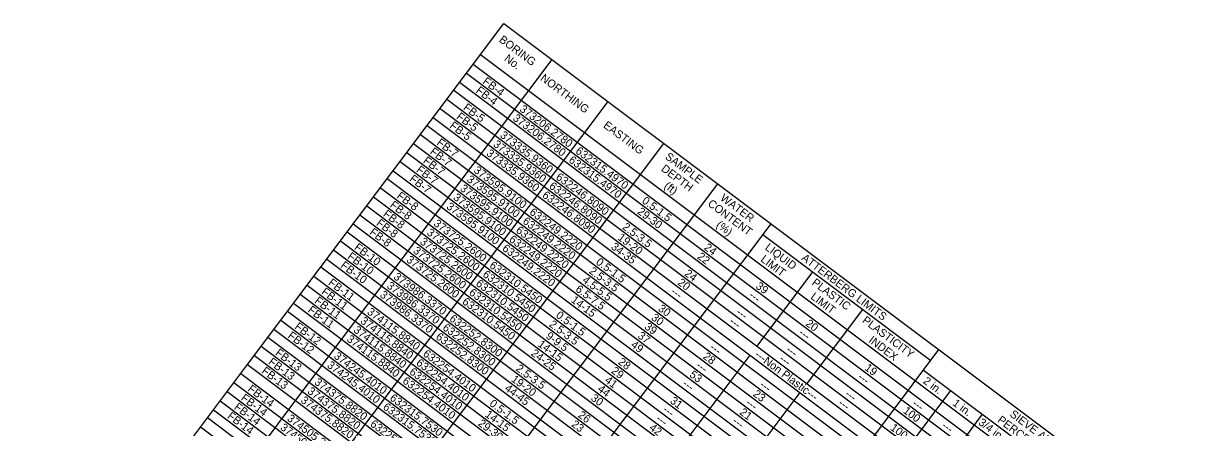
# Model space of a CAD drawing. Extents: x 627484.2 to 627517.5, y 367968.7 to 367996.9.
# Drawn here: x 627484.17 to 627492.24, y 367994.12 to 367996.9 of the extents above; entities that cross this region are included whole.
import ezdxf

# ---------------------------------------------------------------- set-up
doc = ezdxf.new("R2010")
doc.units = 0
doc.layers.add('Default', color=7, linetype='Continuous')
doc.layers.add('R_Survey Control', color=7, linetype='Continuous')

msp = doc.modelspace()

# ---------------------------------------------------------------- linework, layer by layer
at = {"layer": 'Default'}
for p, q in [((627485.7146, 367994.5544), (627487.4769, 367996.9012)), ((627487.4769, 367996.9012), (627492.7198, 367992.9642)), ((627485.9992, 367994.2432), (627487.8082, 367996.6524)), ((627487.3159, 367996.6868), (627492.5588, 367992.7498)), ((627487.2661, 367996.6205), (627491.6592, 367993.3217)), ((627487.1724, 367996.4958), (627492.4153, 367992.5588)), ((627487.2193, 367996.5581), (627491.4252, 367993.3998)), ((627487.1314, 367996.4412), (627492.3744, 367992.5042)), ((627486.383, 367993.955), (627488.192, 367996.3641)), ((627487.0846, 367996.3788), (627492.3275, 367992.4419)), ((627486.9909, 367996.2541), (627492.2338, 367992.3171)), ((627487.0378, 367996.3164), (627492.2807, 367992.3795)), ((627486.95, 367996.1995), (627492.1929, 367992.2625)), ((627486.9031, 367996.1371), (627492.146, 367992.2002)), ((627486.7668, 367993.6668), (627488.5759, 367996.0759)), ((627486.8094, 367996.0124), (627492.0524, 367992.0754)), ((627486.8563, 367996.0747), (627492.0992, 367992.1378)), ((627486.7626, 367995.95), (627492.0055, 367992.013)), ((627486.7158, 367995.8876), (627491.9587, 367991.9507)), ((627486.628, 367995.7707), (627491.8709, 367991.8337)), ((627486.6748, 367995.833), (627491.9177, 367991.8961)), ((627487.1372, 367993.3887), (627488.9462, 367995.7978)), ((627486.5811, 367995.7083), (627491.824, 367991.7713)), ((627486.5343, 367995.6459), (627491.7772, 367991.709)), ((627486.4406, 367995.5212), (627491.6835, 367991.5842)), ((627486.4874, 367995.5836), (627491.7304, 367991.6466)), ((627487.5036, 367993.1135), (627489.3127, 367995.5227)), ((627486.3996, 367995.4666), (627491.6425, 367991.5297)), ((627489.257, 367995.4486), (627490.4109, 367994.5821)), ((627486.3528, 367995.4042), (627491.5957, 367991.4673)), ((627486.2591, 367995.2795), (627491.502, 367991.3425)), ((627486.306, 367995.3419), (627491.5489, 367991.4049)), ((627486.2181, 367995.2249), (627491.461, 367991.288)), ((627486.1713, 367995.1625), (627491.4142, 367991.2256)), ((627489.2166, 367994.6803), (627489.6001, 367995.191)), ((627486.0776, 367995.0378), (627491.3205, 367991.1008)), ((627486.1245, 367995.1002), (627491.3674, 367991.1632)), ((627486.0308, 367994.9754), (627491.2737, 367991.0385)), ((627485.9898, 367994.9208), (627491.2327, 367990.9839)), ((627489.5597, 367994.4227), (627489.9431, 367994.9334)), ((627485.8961, 367994.7961), (627491.139, 367990.8591)), ((627485.943, 367994.8585), (627491.1859, 367990.9215)), ((627485.8552, 367994.7415), (627491.0981, 367990.8046)), ((627485.8083, 367994.6791), (627491.0512, 367990.7422)), ((627488.6575, 367992.247), (627490.4666, 367994.6562)), ((627484.1749, 367992.5039), (627485.7146, 367994.5544)), ((627485.7146, 367994.5544), (627490.9576, 367990.6175)), ((627485.7615, 367994.6168), (627491.0044, 367990.6798)), ((627488.1687, 367993.2847), (627489.1698, 367994.6179)), ((627485.6678, 367994.492), (627490.9107, 367990.5551)), ((627490.3612, 367994.5159), (627491.9517, 367993.3215)), ((627485.621, 367994.4297), (627490.8639, 367990.4927)), ((627485.5741, 367994.3673), (627490.817, 367990.4303)), ((627488.5117, 367993.0271), (627489.5128, 367994.3603)), ((627488.8446, 367992.1065), (627490.5483, 367994.3753)), ((627484.5063, 367992.2551), (627485.9992, 367994.2432)), ((627485.4805, 367994.2425), (627490.7234, 367990.3056)), ((627485.5273, 367994.3049), (627490.7702, 367990.368)), ((627485.4395, 367994.188), (627490.6824, 367990.251)), ((627489.0629, 367991.9426), (627490.7666, 367994.2114)), ((627485.3926, 367994.1256), (627490.6356, 367990.1886))]:
    msp.add_line(p, q, dxfattribs=at)
at = {"layer": 'R_Survey Control'}
msp.add_line((627488.2445, 367996.3247), (627488.2445, 367996.3247), dxfattribs=at)

# ---------------------------------------------------------------- texts
at = {"layer": 'Default'}
for s, p in [('BORING', (627487.4387, 367996.7794)), ('No.', (627487.4743, 367996.6495)), ('FB-4', (627487.3262, 367996.4922)), ('NORTHING', (627487.7227, 367996.5145)), ('FB-4', (627487.2794, 367996.4298)), ('FB-5', (627487.1926, 367996.3121)), ('373206.2780', (627487.58, 367996.3016)), ('FB-5', (627487.1457, 367996.2498)), ('373206.2780', (627487.5332, 367996.2392)), ('FB-5', (627487.0989, 367996.1874)), ('EASTING', (627488.1548, 367996.1901)), ('FB-7', (627487.0104, 367996.0709)), ('373335.9360', (627487.3985, 367996.0599)), ('373335.9360', (627487.4454, 367996.1223)), ('FB-7', (627486.9635, 367996.0086)), ('373335.9360', (627487.3517, 367995.9976)), ('632315.4970', (627487.9638, 367996.0134)), ('SAMPLE', (627488.5795, 367995.9743)), ('FB-7', (627486.8699, 367995.8838)), ('FB-7', (627486.9167, 367995.9462)), ('632315.4970', (627487.917, 367995.951)), ('DEPTH', (627488.5526, 367995.8913)), ('FB-7', (627486.823, 367995.8215)), ('373595.9100', (627487.217, 367995.8182)), ('373595.9100', (627487.2639, 367995.8806)), ('632246.8090', (627487.8292, 367995.8341)), ('373595.9100', (627487.1702, 367995.7559)), ('632246.8090', (627487.7824, 367995.7717)), ('(ft)', (627488.5724, 367995.7733)), ('FB-8', (627486.6888, 367995.6418)), ('FB-8', (627486.7356, 367995.7042)), ('373595.9100', (627487.1234, 367995.6935)), ('632246.8090', (627487.7355, 367995.7093)), ('0.5-1.5', (627488.4205, 367995.6705)), ('CONTENT', (627488.8728, 367995.6509)), ('WATER', (627488.9588, 367995.6895)), ('FB-8', (627486.6419, 367995.5795)), ('373595.9100', (627487.0765, 367995.6311)), ('632249.2220', (627487.6477, 367995.5924)), ('29-30', (627488.3889, 367995.5967)), ('FB-8', (627486.5951, 367995.5171)), ('373725.2600', (627486.9887, 367995.5142)), ('632249.2220', (627487.6009, 367995.53)), ('2.5-3.5', (627488.2858, 367995.4912)), ('(%)', (627488.93, 367995.5048)), ('FB-8', (627486.5483, 367995.4547)), ('373725.2600', (627486.9419, 367995.4518)), ('632249.2220', (627487.5072, 367995.4053)), ('632249.2220', (627487.554, 367995.4676)), ('19-20', (627488.2542, 367995.4174)), ('FB-10', (627486.4435, 367995.3505)), ('373725.2600', (627486.8482, 367995.327)), ('373725.2600', (627486.895, 367995.3894)), ('632249.2220', (627487.4604, 367995.3429)), ('34-35', (627488.2084, 367995.3543)), ('24', (627488.8474, 367995.3499)), ('LIQUID', (627489.2662, 367995.3492)), ('FB-10', (627486.3967, 367995.2881)), ('373725.2600', (627486.8014, 367995.2647)), ('0.5-1.5', (627488.1043, 367995.2495)), ('22', (627488.8008, 367995.2874)), ('LIMIT', (627489.2363, 367995.2684)), ('ATTERBERG LIMITS', (627489.5167, 367995.2771)), ('FB-10', (627486.3498, 367995.2257)), ('632310.5450', (627487.3257, 367995.1636)), ('632310.5450', (627487.3725, 367995.2259)), ('2.5-3.5', (627488.0575, 367995.1871)), ('24', (627488.7127, 367995.1706)), ('FB-11', (627486.2648, 367995.1067)), ('373986.3370', (627486.6667, 367995.0853)), ('373986.3370', (627486.7135, 367995.1477)), ('632310.5450', (627487.2789, 367995.1012)), ('4.5-5.5', (627488.0106, 367995.1248)), ('20', (627488.6659, 367995.1082)), ('39', (627489.2024, 367995.0834)), ('PLASTIC', (627489.588, 367995.1075)), ('FB-11', (627486.218, 367995.0443)), ('373986.3370', (627486.6199, 367995.023)), ('632310.5450', (627487.232, 367995.0388)), ('6.5-7.5', (627487.9638, 367995.0624)), ('---', (627488.6192, 367995.0457)), ('---', (627489.1555, 367995.021)), ('LIMIT', (627489.5794, 367995.0108)), ('FB-11', (627486.1243, 367994.9196)), ('FB-11', (627486.1712, 367994.9819)), ('632310.5450', (627487.1852, 367994.9764)), ('14-15', (627487.9332, 367994.9878)), ('30', (627488.5313, 367994.9289)), ('374115.8840', (627486.4852, 367994.8437)), ('374115.8840', (627486.532, 367994.906)), ('632252.8300', (627487.0974, 367994.8595)), ('0.5-1.5', (627487.8292, 367994.8831)), ('30', (627488.4844, 367994.8665)), ('---', (627489.0677, 367994.9041)), ('PLASTICITY', (627489.9342, 367994.8476)), ('FB-12', (627486.0339, 367994.8046)), ('374115.8840', (627486.4384, 367994.7813)), ('632252.8300', (627487.0505, 367994.7971)), ('2.5-3.5', (627487.7823, 367994.8207)), ('39', (627488.4378, 367994.804)), ('---', (627489.0208, 367994.8417)), ('20', (627489.5452, 367994.8259)), ('FB-12', (627485.987, 367994.7422)), ('374115.8840', (627486.3915, 367994.7189)), ('632252.8300', (627487.0037, 367994.7348)), ('14-15', (627487.7049, 367994.6838)), ('9-9.5', (627487.7598, 367994.74)), ('37', (627488.3911, 367994.7416)), ('---', (627489.4985, 367994.7634)), ('INDEX', (627489.9784, 367994.7112)), ('FB-13', (627485.9006, 367994.6242)), ('374245.4010', (627486.3037, 367994.602)), ('632254.4010', (627486.9159, 367994.6178)), ('24-25', (627487.658, 367994.6214)), ('49', (627488.3441, 367994.6792)), ('28', (627488.8399, 367994.5996)), ('---', (627488.8862, 367994.6624)), ('---Non Plastic---', (627489.1963, 367994.6124)), ('---', (627489.4107, 367994.6465)), ('FB-13', (627485.8537, 367994.5619)), ('374245.4010', (627486.2569, 367994.5396)), ('632254.4010', (627486.869, 367994.5554)), ('2.5-3.5', (627487.554, 367994.5166)), ('28', (627488.2568, 367994.5619)), ('---', (627488.7925, 367994.5377)), ('---', (627489.3639, 367994.5841)), ('19', (627489.9509, 367994.5213)), ('FB-13', (627485.8069, 367994.4995)), ('632254.4010', (627486.7754, 367994.4307)), ('632254.4010', (627486.8222, 367994.4931)), ('19-20', (627487.5224, 367994.4428)), ('29', (627488.2095, 367994.4999)), ('53', (627488.747, 367994.4742)), ('---', (627489.9039, 367994.459)), ('FB-14', (627485.7117, 367994.3759)), ('374375.8820', (627486.1222, 367994.3603)), ('374375.8820', (627486.1691, 367994.4226)), ('44-45', (627487.4765, 367994.3797)), ('44', (627488.1156, 367994.3754)), ('41', (627488.1653, 367994.4356)), ('---', (627488.6988, 367994.4129)), ('---', (627489.2292, 367994.4048)), ('2 in.', (627490.3522, 367994.4303)), ('FB-14', (627485.6648, 367994.3136)), ('374375.8820', (627486.0754, 367994.2979)), ('632315.7530', (627486.6876, 367994.3137)), ('0.5-1.5', (627487.3725, 367994.2749)), ('30', (627488.0688, 367994.313)), ('31', (627488.6137, 367994.294)), ('23', (627489.1838, 367994.3414)), ('---', (627489.8161, 367994.3421)), ('1 in.', (627490.5549, 367994.2781)), ('FB-14', (627485.5711, 367994.1888)), ('FB-14', (627485.618, 367994.2512)), ('632315.7530', (627486.6407, 367994.2514)), ('14-15', (627487.3419, 367994.2004)), ('26', (627487.981, 367994.196)), ('---', (627488.5642, 367994.2336)), ('21', (627489.0914, 367994.2157)), ('---', (627489.1355, 367994.2801)), ('---', (627489.7693, 367994.2797)), ('100', (627490.215, 367994.2254)), ('---', (627490.2782, 367994.2755)), ('SIEVE ANALYSIS', (627490.9485, 367994.2018)), ('374505.2580', (627485.9349, 367994.1108)), ('374505.2580', (627485.9817, 367994.1731)), ('632257.0140', (627486.5529, 367994.1344)), ('29-30', (627487.2941, 367994.1387)), ('23', (627487.9356, 367994.1325)), ('---', (627488.5173, 367994.1712)), ('---', (627489.0419, 367994.1553)), ('3/4 in.', (627490.7323, 367994.1449)), ('PERCENT PASSING', (627490.8637, 367994.1623)), ('42', (627488.4705, 367994.1088)), ('100', (627490.1272, 367994.1085)), ('---', (627490.481, 367994.1233))]:
    msp.add_text(s, height=0.055, rotation=323.09678, dxfattribs=at).set_placement(p)

doc.saveas('drawing.dxf')
